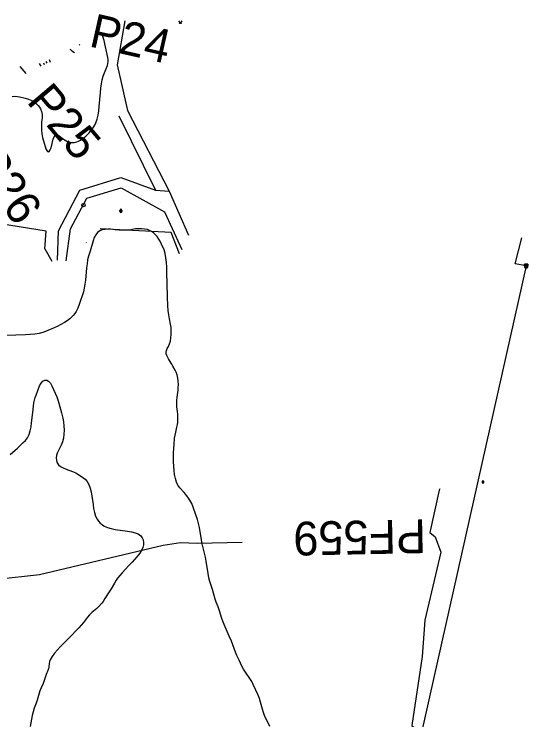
# Model space of a CAD drawing. Extents: x -737422 to -734235, y -1145631 to -1142623.
# Drawn here: x -734908.1 to -734755.5, y -1142981.5 to -1142772 of the extents above; entities that cross this region are included whole.
import ezdxf

# ---------------------------------------------------------------- set-up
doc = ezdxf.new("R2010")
doc.units = 0
for name, color, linetype in [('Vrstva 1', 7, 'Continuous'), ('Vrstva 19', 7, 'Continuous'), ('Vrstva 20', 7, 'Continuous'), ('Vrstva 22', 7, 'Continuous'), ('Vrstva 29', 7, 'Continuous'), ('Vrstva 3', 7, 'Continuous'), ('Vrstva 46', 7, 'Continuous'), ('Vrstva 8', 7, 'Continuous'), ('Vrstva 9', 7, 'Continuous')]:
    doc.layers.add(name, color=color, linetype=linetype)

# ---------------------------------------------------------------- blocks, each defined once
blk = doc.blocks.new('6.200')
at = {"layer": 'Vrstva 1'}
blk.add_circle((0, 0), 1, dxfattribs=at)
blk = doc.blocks.new('3.140')
at = {"layer": 'Vrstva 1'}
blk.add_lwpolyline([(-1, 1.5), (0, 0), (1, 1.5)], dxfattribs=at)
for centre in [(-0.5, 0.1), (0.5, 0.1)]:
    blk.add_circle(centre, 0.1, dxfattribs=at)
blk = doc.blocks.new('3.160')
at = {"layer": 'Vrstva 1'}
for p, q in [((-1, 0), (1, 0)), ((-0.5, -0.5), (-0.5, 0.5)), ((0.5, -0.5), (0.5, 0.5))]:
    blk.add_line(p, q, dxfattribs=at)
for centre, start, end in [((0, 0.5), 0, 180), ((0, -0.5), 180, 360)]:
    blk.add_arc(centre, 0.5, start, end, dxfattribs=at)
blk = doc.blocks.new('6.111')
at = {"layer": 'Vrstva 1'}
blk.add_line((0, -2), (0, -1), dxfattribs=at)
blk.add_lwpolyline([(-1, 0), (-1, 1), (1, 1), (1, 0)], dxfattribs=at)
blk.add_lwpolyline([(-1, -1), (1, -1), (1, 0), (-1, 0)], close=True, dxfattribs=at)
blk = doc.blocks.new('6.081')
at = {"layer": 'Vrstva 1'}
for p, q in [((1, 1), (-1, 1)), ((-1, 1), (-1, -1)), ((1, -1), (1, 1)), ((-1, -1), (1, -1))]:
    blk.add_line(p, q, dxfattribs=at)
blk = doc.blocks.new('6.301')
at = {"layer": 'Vrstva 1'}
blk.add_line((-0.5, 0), (0.5, 0), dxfattribs=at)
blk.add_lwpolyline([(-0.5, -0.502), (0.501, -0.502), (0.501, 0.501), (-0.5, 0.501)], close=True, dxfattribs=at)

msp = doc.modelspace()

# ---------------------------------------------------------------- linework, layer by layer
at = {"layer": 'Vrstva 1'}
for points in [[(-734891.899, -1142809.863), (-734891.131, -1142810.031), (-734890.325, -1142810.038), (-734889.534, -1142809.878), (-734888.975, -1142809.646), (-734888.43, -1142809.35), (-734887.882, -1142809.014), (-734887.347, -1142808.633), (-734886.842, -1142808.196), (-734885.863, -1142807.236), (-734885.393, -1142806.717), (-734884.962, -1142806.15), (-734884.171, -1142804.927), (-734883.824, -1142804.261), (-734883.432, -1142803.175), (-734883.153, -1142801.975), (-734882.953, -1142800.694), (-734882.807, -1142799.362), (-734882.481, -1142795.272), (-734882.353, -1142793.944), (-734882.186, -1142792.669), (-734881.961, -1142791.472), (-734881.656, -1142790.383), (-734880.867, -1142788.441), (-734880.413, -1142787.248), (-734880.245, -1142786.669), (-734880.162, -1142786.073), (-734880.169, -1142785.468), (-734880.258, -1142784.863), (-734880.924, -1142781.65), (-734881.14, -1142780.74), (-734881.394, -1142779.841), (-734881.873, -1142778.357), (-734882.076, -1142777.513)], [(-734908.658, -1142796.458), (-734907.885, -1142796.34), (-734907.077, -1142796.375), (-734906.472, -1142796.497), (-734904.852, -1142796.94), (-734903.821, -1142797.256), (-734902.824, -1142797.647), (-734901.932, -1142798.157), (-734901.425, -1142798.582), (-734900.977, -1142799.055), (-734900.576, -1142799.556), (-734900.244, -1142800.1), (-734899.947, -1142800.915), (-734899.803, -1142801.799), (-734899.794, -1142802.703), (-734899.943, -1142804.065), (-734900.02, -1142805.168), (-734900.019, -1142806.319), (-734899.929, -1142807.463), (-734899.732, -1142808.544), (-734898.877, -1142811.309), (-734898.66, -1142811.937), (-734898.428, -1142812.433), (-734898.165, -1142812.739), (-734897.919, -1142812.81), (-734897.676, -1142812.709), (-734897.387, -1142812.283), (-734897.155, -1142811.617), (-734896.532, -1142809.134), (-734896.262, -1142808.436), (-734895.912, -1142807.955), (-734895.607, -1142807.796), (-734895.279, -1142807.788), (-734894.841, -1142807.991), (-734893.859, -1142808.772), (-734893.408, -1142809.075), (-734892.426, -1142809.638), (-734891.899, -1142809.863)], [(-734869.371, -1142835.756), (-734870.259, -1142835.663), (-734871.158, -1142835.657), (-734872.043, -1142835.732), (-734873.479, -1142835.971), (-734874.615, -1142836.099), (-734875.79, -1142836.146), (-734876.96, -1142836.118), (-734878.077, -1142836.015), (-734879.465, -1142835.825), (-734880.304, -1142835.793), (-734881.142, -1142835.858), (-734881.947, -1142836.03), (-734882.687, -1142836.326), (-734883.326, -1142836.768), (-734883.886, -1142837.449), (-734884.32, -1142838.288), (-734884.67, -1142839.234), (-734885.557, -1142842.315), (-734886.032, -1142843.846), (-734886.278, -1142844.94), (-734886.462, -1142846.098), (-734886.603, -1142847.298), (-734886.953, -1142850.973), (-734887.1, -1142852.166), (-734887.292, -1142853.313), (-734887.55, -1142854.394), (-734888.785, -1142858.173), (-734889.196, -1142859.265), (-734889.704, -1142860.26), (-734890.117, -1142860.848), (-734890.572, -1142861.395), (-734891.05, -1142861.918), (-734891.566, -1142862.403), (-734892.338, -1142862.967), (-734893.17, -1142863.47), (-734895.283, -1142864.695), (-734896.192, -1142865.122), (-734898.815, -1142866.174), (-734899.55, -1142866.442), (-734900.723, -1142866.748), (-734901.989, -1142866.96), (-734903.325, -1142867.105), (-734904.709, -1142867.2), (-734907.574, -1142867.295), (-734911.981, -1142867.318)], [(-734859.757, -1142888.535), (-734859.828, -1142887.585), (-734859.816, -1142886.618), (-734859.719, -1142885.664), (-734859.473, -1142884.267), (-734859.388, -1142883.589), (-734859.337, -1142882.885), (-734859.323, -1142881.92), (-734859.371, -1142880.949), (-734859.488, -1142879.994), (-734859.681, -1142879.08), (-734859.964, -1142878.233), (-734860.263, -1142877.606), (-734860.929, -1142876.428), (-734861.273, -1142875.866), (-734861.972, -1142874.824), (-734862.271, -1142874.307), (-734862.751, -1142873.314), (-734862.9, -1142872.836), (-734862.944, -1142872.347), (-734862.876, -1142871.861), (-734862.63, -1142871.237), (-734862.288, -1142870.599), (-734861.949, -1142869.884), (-734861.693, -1142869.045), (-734861.527, -1142868.102), (-734861.442, -1142867.092), (-734861.435, -1142866.046), (-734861.505, -1142864.991), (-734861.658, -1142863.954), (-734861.998, -1142862.424), (-734862.205, -1142861.215), (-734862.355, -1142859.924), (-734862.46, -1142858.572), (-734862.581, -1142855.749), (-734862.721, -1142848.473), (-734862.783, -1142847.05), (-734862.88, -1142845.662), (-734863.029, -1142844.328), (-734863.253, -1142843.068), (-734863.578, -1142841.912), (-734863.868, -1142841.194), (-734864.188, -1142840.508), (-734864.622, -1142839.605), (-734865.088, -1142838.742), (-734865.627, -1142837.964), (-734866.101, -1142837.46), (-734866.616, -1142837.009), (-734867.156, -1142836.599), (-734867.74, -1142836.251), (-734868.522, -1142835.947), (-734869.371, -1142835.756)], [(-734909.296, -1142902.65), (-734907.148, -1142900.779), (-734905.412, -1142899.156), (-734904.737, -1142898.484), (-734904.151, -1142897.72), (-734903.685, -1142896.768), (-734903.347, -1142895.684), (-734903.101, -1142894.504), (-734902.918, -1142893.26), (-734902.505, -1142889.381), (-734902.342, -1142888.117), (-734902.13, -1142886.908), (-734901.844, -1142885.786), (-734901.587, -1142885.049), (-734900.542, -1142882.329), (-734900.114, -1142881.499), (-734899.599, -1142880.904), (-734899.043, -1142880.644), (-734898.448, -1142880.64), (-734897.887, -1142880.892), (-734897.358, -1142881.476), (-734896.908, -1142882.29), (-734895.444, -1142885.614), (-734895.127, -1142886.507), (-734894.85, -1142887.449), (-734894.081, -1142890.324), (-734893.636, -1142891.855), (-734893.421, -1142893.01), (-734893.307, -1142894.215), (-734893.284, -1142895.442), (-734893.347, -1142896.659), (-734893.498, -1142897.837), (-734893.744, -1142898.943), (-734894.099, -1142899.939), (-734894.528, -1142900.748), (-734894.975, -1142901.493)], [(-734846.023, -1142952.437), (-734846.429, -1142951.342), (-734847.137, -1142949.05), (-734847.521, -1142947.934), (-734848.092, -1142946.505), (-734848.395, -1142945.608), (-734849.179, -1142942.791), (-734849.462, -1142941.874), (-734849.971, -1142940.383), (-734850.266, -1142939.249), (-734850.497, -1142938.052), (-734851.057, -1142934.326), (-734851.273, -1142933.113), (-734851.541, -1142931.952), (-734851.991, -1142930.401), (-734852.26, -1142929.241), (-734852.478, -1142928.029), (-734853.054, -1142924.316), (-734853.298, -1142923.13), (-734853.611, -1142922.012), (-734854.161, -1142920.559), (-734854.946, -1142918.337), (-734855.371, -1142917.257), (-734855.878, -1142916.259), (-734856.28, -1142915.657), (-734857.147, -1142914.515), (-734857.601, -1142913.965), (-734858.885, -1142912.57), (-734859.449, -1142911.795), (-734859.897, -1142910.853), (-734860.219, -1142909.79), (-734860.446, -1142908.635), (-734860.599, -1142907.413), (-734860.696, -1142906.145), (-734860.748, -1142904.847), (-734860.763, -1142903.533), (-734860.745, -1142902.215), (-734860.696, -1142900.907), (-734860.614, -1142899.621), (-734860.429, -1142897.831), (-734860.289, -1142896.914), (-734860.115, -1142896.044), (-734859.743, -1142894.531), (-734859.612, -1142893.825), (-734859.521, -1142893.106), (-734859.463, -1142892.32), (-734859.447, -1142891.54), (-734859.474, -1142890.715), (-734859.549, -1142889.924), (-734859.757, -1142888.535)], [(-734894.975, -1142901.493), (-734895.347, -1142902.242), (-734895.549, -1142902.961), (-734895.615, -1142903.702), (-734895.542, -1142904.431), (-734895.323, -1142905.113), (-734894.939, -1142905.71), (-734894.311, -1142906.24), (-734893.52, -1142906.664), (-734892.626, -1142907.024), (-734890.729, -1142907.717), (-734889.821, -1142908.13), (-734889.189, -1142908.495), (-734887.783, -1142909.429), (-734887.034, -1142910.023), (-734886.393, -1142910.727), (-734885.883, -1142911.63), (-734885.513, -1142912.673), (-734885.24, -1142913.814), (-734885.031, -1142915.019), (-734884.683, -1142917.499), (-734884.488, -1142918.719), (-734884.24, -1142919.885), (-734883.904, -1142920.965), (-734883.44, -1142921.918), (-734883.012, -1142922.502), (-734882.522, -1142923.025), (-734881.986, -1142923.503), (-734881.388, -1142923.92), (-734880.416, -1142924.368), (-734879.318, -1142924.691), (-734878.136, -1142924.927), (-734874.429, -1142925.442), (-734873.252, -1142925.645), (-734872.167, -1142925.913), (-734871.223, -1142926.283), (-734870.478, -1142926.796), (-734870.038, -1142927.373), (-734869.771, -1142928.047), (-734869.658, -1142928.776), (-734869.691, -1142929.522), (-734869.867, -1142930.249), (-734870.121, -1142930.82), (-734870.791, -1142931.941), (-734871.184, -1142932.494), (-734871.623, -1142933.024), (-734873.026, -1142934.615), (-734874.029, -1142935.645), (-734875.999, -1142937.763), (-734877.378, -1142939.442), (-734877.816, -1142940.022), (-734878.343, -1142940.85)], [(-734781.69, -1142912.92), (-734781.87, -1142913.23), (-734784.58, -1142925.84), (-734783.05, -1142927.09), (-734781.38, -1142931.68), (-734786.12, -1142951.87), (-734786.89, -1142962.61), (-734789.96, -1142983.14), (-734786.47, -1142986.1), (-734790.29, -1143002.11), (-734792.32, -1143005.42), (-734795.76, -1143009.87), (-734828.54, -1143144.22)], [(-734878.343, -1142940.85), (-734879.33, -1142942.563), (-734880.125, -1142943.788), (-734881.122, -1142945.479), (-734881.659, -1142946.284), (-734882.11, -1142946.839), (-734883.062, -1142947.897), (-734883.56, -1142948.404), (-734885.009, -1142949.633), (-734885.705, -1142950.276), (-734886.325, -1142950.995), (-734887.49, -1142952.509), (-734888.908, -1142954.104), (-734889.384, -1142954.632), (-734891.354, -1142956.672), (-734892.361, -1142957.66), (-734893.327, -1142958.674), (-734894.302, -1142959.653), (-734896.074, -1142961.641), (-734896.803, -1142962.656), (-734897.127, -1142963.151), (-734897.4, -1142963.648), (-734897.598, -1142964.166), (-734897.722, -1142964.689), (-734897.851, -1142965.725), (-734897.95, -1142966.274), (-734898.104, -1142966.837), (-734898.55, -1142967.988), (-734899.18, -1142969.725), (-734899.532, -1142970.625), (-734900.123, -1142971.967), (-734900.44, -1142972.834), (-734901.281, -1142975.606), (-734901.587, -1142976.517), (-734902.142, -1142977.993), (-734902.454, -1142979.033), (-734902.712, -1142980.12), (-734903.358, -1142983.407)], [(-734832.148, -1142983.458), (-734833.705, -1142980.194), (-734834.06, -1142979.252), (-734834.362, -1142978.249), (-734834.909, -1142976.176), (-734835.205, -1142975.158), (-734835.597, -1142974.076), (-734837.064, -1142970.957), (-734837.508, -1142970.115), (-734839.956, -1142966.384), (-734840.429, -1142965.521), (-734841.302, -1142963.723), (-734841.976, -1142962.396), (-734842.398, -1142961.356), (-734843.139, -1142959.174), (-734843.541, -1142958.115), (-734844.225, -1142956.64), (-734845.395, -1142953.809), (-734846.023, -1142952.437)]]:
    msp.add_lwpolyline(points, dxfattribs=at)
at = {"layer": 'Vrstva 19'}
msp.add_lwpolyline([(-734755.99, -1142846.67), (-734759.24, -1142846.09), (-734757.28, -1142838.39)], dxfattribs=at)
at = {"layer": 'Vrstva 20'}
for points in [[(-734875.205, -1142773.979), (-734877.55, -1142787.01), (-734874.39, -1142800.55), (-734862.04, -1142824.53)], [(-734888.84, -1142780.991), (-734888.56, -1142781.2)], [(-734891.528, -1142782.373), (-734891.35, -1142782.51), (-734890.95, -1142782.82), (-734890.21, -1142783.37)], [(-734900.656, -1142786.589), (-734900.22, -1142787.38)], [(-734899.401, -1142786.393), (-734899.15, -1142786.9)], [(-734898.34, -1142786.57), (-734898.576, -1142785.998)], [(-734897.27, -1142786.32), (-734897.629, -1142785.511)], [(-734877.02, -1142802.12), (-734866.09, -1142824.25)], [(-734888.6, -1142824.24), (-734876.37, -1142820.46)], [(-734876.37, -1142820.46), (-734866.09, -1142824.25)], [(-734894.94, -1142836.26), (-734888.6, -1142824.24)], [(-734886.5, -1142826.62), (-734876.32, -1142823.5)], [(-734876.32, -1142823.5), (-734863.47, -1142830.65)], [(-734866.09, -1142824.25), (-734862.04, -1142824.53)], [(-734862.04, -1142824.53), (-734856.32, -1142837.62)], [(-734891.4, -1142835.73), (-734886.5, -1142826.62)], [(-734899.03, -1142841.66), (-734898.63, -1142836.39), (-734934.42, -1142830.68), (-734937.29, -1142835.06), (-734941.61, -1142853.97), (-734943.23, -1142861.05), (-734970.48, -1142856.73), (-735008.81, -1142850.65)], [(-734863.47, -1142830.65), (-734858.34, -1142841.8)], [(-734895.26, -1142844.99), (-734894.94, -1142836.26)], [(-734892.64, -1142845.17), (-734891.4, -1142835.73)], [(-734861.51, -1142836.78), (-734882.54, -1142835.72)], [(-734858.98, -1142843.13), (-734861.51, -1142836.78)], [(-734899.03, -1142841.66), (-734896.95, -1142845.33)], [(-734755.99, -1142846.67), (-734790.73, -1143001.58), (-734821.04, -1143128.56)]]:
    msp.add_lwpolyline(points, dxfattribs=at)
at = {"layer": 'Vrstva 3'}
for points in [[(-734900.656, -1142786.589), (-734900.22, -1142787.38)], [(-734897.27, -1142786.32), (-734897.629, -1142785.511)]]:
    msp.add_lwpolyline(points, dxfattribs=at)
at = {"layer": 'Vrstva 8'}
for points in [[(-734906.426, -1142787.49), (-734904.66, -1142789.57)], [(-735118.71, -1142932.59), (-735071.5, -1142935.89), (-735064.42, -1142936.68), (-735056.34, -1142937.73), (-735055.74, -1142937.81), (-735055.59, -1142937.83), (-735054.09, -1142938.02), (-735050.82, -1142938.44), (-735047.01, -1142938.94), (-735042.35, -1142939.54), (-735036.84, -1142940.26), (-735035.44, -1142940.44), (-735033.43, -1142940.7), (-735020.82, -1142941.83), (-734985.35, -1142941.99), (-734917.54, -1142940.07), (-734915.94, -1142939.6), (-734913.24, -1142939.73), (-734900.57, -1142938.31), (-734863.85, -1142929.62), (-734858.72, -1142928.81), (-734853.77, -1142928.99), (-734840.4, -1142928.73)]]:
    msp.add_lwpolyline(points, dxfattribs=at)

# ---------------------------------------------------------------- block references
at = {"layer": 'Vrstva 20', "xscale": 0.5, "yscale": 0.5}
for name, p in [('3.140', (-734858.74, -1142774.72)), ('6.200', (-734887.51, -1142828.66)), ('3.160', (-734876.41, -1142830.37))]:
    msp.add_blockref(name, p, dxfattribs=at)
at = {"layer": 'Vrstva 29', "xscale": 0.5, "yscale": 0.5}
for name in ['6.111', '6.081']:
    msp.add_blockref(name, (-734755.99, -1142846.67), dxfattribs=at)
at = {"layer": 'Vrstva 46', "xscale": 0.5, "yscale": 0.5}
msp.add_blockref('6.301', (-734768.79, -1142910.83), dxfattribs=at)

# ---------------------------------------------------------------- texts
at = {"layer": 'Vrstva 22'}
for s, p in [('asf.', (-734864.66, -1142827.84)), ('trafo', (-734887.14, -1142839.85))]:
    msp.add_text(s, height=0.3, dxfattribs=at).set_placement(p)
at = {"layer": 'Vrstva 9'}
for s, rotation, p in [('P24', 347.307, (-734886.17, -1142781.48)), ('P25', 310.339, (-734904.66, -1142797.99)), ('P26', 303.744, (-734920.83, -1142815.48)), ('PF559', 181.114, (-734785.84, -1142921.94))]:
    msp.add_text(s, height=10, rotation=rotation, dxfattribs=at).set_placement(p)

doc.saveas('drawing.dxf')
